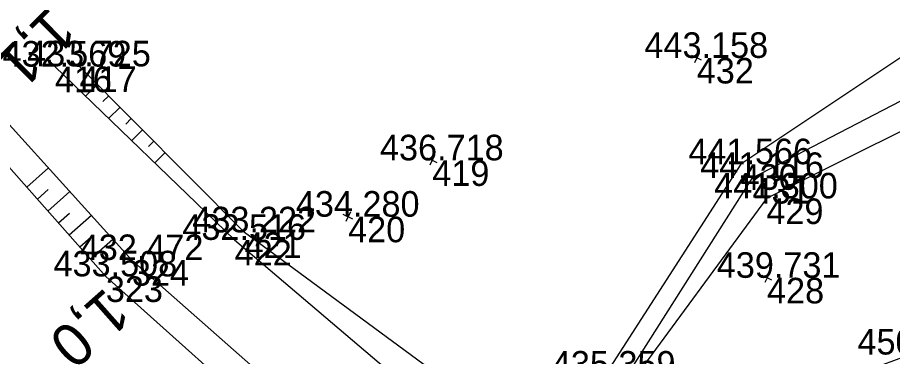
# Model space of a CAD drawing. Extents: x -751615 to -750797, y -1114905 to -1114561.
# Drawn here: x -751104.04 to -751063.01, y -1114657.37 to -1114641.47 of the extents above; entities that cross this region are included whole.
import ezdxf

# ---------------------------------------------------------------- set-up
doc = ezdxf.new("R2010")
doc.units = 0
for name, color, linetype in [('Vrstva 18', 7, 'Continuous'), ('Vrstva 48', 7, 'Continuous'), ('Vrstva 49', 7, 'Continuous'), ('Vrstva 50', 7, 'Continuous'), ('Vrstva 60', 7, 'Continuous'), ('Vrstva 61', 7, 'Continuous')]:
    doc.layers.add(name, color=color, linetype=linetype)

msp = doc.modelspace()

# ---------------------------------------------------------------- linework, layer by layer
at = {"layer": 'Vrstva 18'}
msp.add_ellipse((-751065.634, -1114658.626), major_axis=(5.471, 2.11), ratio=0.004805, start_param=0.014809, end_param=1.725149, dxfattribs=at)
at = {"layer": 'Vrstva 48'}
for p, q in [((-751100.291, -1114644.609), (-751100.846, -1114645.161)), ((-751099.762, -1114645.141), (-751100.034, -1114645.411)), ((-751099.234, -1114645.673), (-751099.766, -1114646.202)), ((-751098.705, -1114646.205), (-751098.966, -1114646.464)), ((-751098.176, -1114646.736), (-751098.686, -1114647.243)), ((-751097.647, -1114647.268), (-751097.897, -1114647.516)), ((-751097.119, -1114647.8), (-751097.606, -1114648.285)), ((-751103.607, -1114649.422), (-751102.589, -1114648.521)), ((-751103.11, -1114649.984), (-751102.598, -1114649.53)), ((-751102.613, -1114650.545), (-751101.582, -1114649.633)), ((-751102.115, -1114651.107), (-751101.597, -1114650.648)), ((-751101.618, -1114651.668), (-751100.576, -1114650.745)), ((-751101.121, -1114652.23), (-751100.597, -1114651.766)), ((-751100.624, -1114652.792), (-751099.569, -1114651.858))]:
    msp.add_line(p, q, dxfattribs=at)
at = {"layer": 'Vrstva 49'}
for p, q in [((-751071.962, -1114643.472), (-751072.412, -1114643.254)), ((-751072.078, -1114643.138), (-751072.296, -1114643.588)), ((-751084.363, -1114648.279), (-751084.813, -1114648.059)), ((-751084.478, -1114647.944), (-751084.698, -1114648.394)), ((-751088.311, -1114650.921), (-751088.761, -1114650.701)), ((-751088.426, -1114650.586), (-751088.646, -1114651.036)), ((-751068.666, -1114653.788), (-751069.116, -1114653.57)), ((-751068.782, -1114653.454), (-751069, -1114653.904))]:
    msp.add_line(p, q, dxfattribs=at)
for points in [[(-751116.675, -1114632.953), (-751098.674, -1114652.847), (-751090.21, -1114660.329), (-751083.98, -1114663.255), (-751079.08, -1114670.424), (-751065.412, -1114686.286)], [(-751117.644, -1114633.563), (-751099.898, -1114653.612), (-751091.377, -1114661.254), (-751084.998, -1114664.191), (-751079.852, -1114671.705), (-751066.794, -1114687.156)], [(-751020.117, -1114634.765), (-751060.04, -1114641.62), (-751070.127, -1114648.352), (-751076.528, -1114658.314), (-751078.11, -1114663.715)], [(-751019.246, -1114637.748), (-751058.49, -1114644.759), (-751068.921, -1114649.956), (-751075.459, -1114658.878), (-751078.11, -1114663.715)], [(-751102.288, -1114643.771), (-751093.857, -1114651.899), (-751082.797, -1114661.315), (-751076.158, -1114667.661), (-751071.168, -1114674.163), (-751065.653, -1114680.07)], [(-751078.11, -1114663.715), (-751081.827, -1114660.07), (-751093.394, -1114651.547), (-751101.134, -1114643.761)], [(-751078.11, -1114663.715), (-751075.662, -1114658.603), (-751069.572, -1114648.996), (-751058.95, -1114643.469)]]:
    msp.add_lwpolyline(points, dxfattribs=at)
at = {"layer": 'Vrstva 50'}
for points in [[(-751116.675, -1114632.953), (-751098.674, -1114652.847), (-751090.21, -1114660.329), (-751083.98, -1114663.255), (-751079.08, -1114670.424), (-751065.412, -1114686.286)], [(-751102.288, -1114643.771), (-751093.857, -1114651.899), (-751082.797, -1114661.315), (-751076.158, -1114667.661), (-751071.168, -1114674.163), (-751065.653, -1114680.07)]]:
    msp.add_lwpolyline(points, dxfattribs=at)
at = {"layer": 'Vrstva 60'}
for p, q in [((-751072.187, -1114643.363), (-751072.187, -1114643.363)), ((-751102.288, -1114643.771), (-751102.288, -1114643.771)), ((-751101.134, -1114643.761), (-751101.134, -1114643.761)), ((-751084.588, -1114648.169), (-751084.588, -1114648.169)), ((-751070.127, -1114648.352), (-751070.127, -1114648.352)), ((-751069.572, -1114648.996), (-751069.572, -1114648.996)), ((-751068.921, -1114649.956), (-751068.921, -1114649.956)), ((-751088.536, -1114650.811), (-751088.536, -1114650.811)), ((-751093.394, -1114651.547), (-751093.394, -1114651.547)), ((-751093.857, -1114651.899), (-751093.857, -1114651.899)), ((-751098.674, -1114652.847), (-751098.674, -1114652.847)), ((-751099.898, -1114653.612), (-751099.898, -1114653.612)), ((-751068.891, -1114653.679), (-751068.891, -1114653.679))]:
    msp.add_line(p, q, dxfattribs=at)

# ---------------------------------------------------------------- texts
at = {"layer": 'Vrstva 48'}
for s, rotation, p in [('1,1', 224.8302, (-751102.533, -1114640.88)), ('1,0', 221.5131, (-751099.911, -1114654.087))]:
    msp.add_text(s, height=2, rotation=rotation, dxfattribs=at).set_placement(p)
at = {"layer": 'Vrstva 60'}
for s, p in [('432', (-751072.187, -1114644.563)), ('416', (-751102.288, -1114644.971)), ('417', (-751101.134, -1114644.961)), ('419', (-751084.588, -1114649.369)), ('430', (-751070.127, -1114649.552)), ('431', (-751069.572, -1114650.196)), ('429', (-751068.921, -1114651.156)), ('420', (-751088.536, -1114652.011)), ('421', (-751093.394, -1114652.747)), ('422', (-751093.857, -1114653.099)), ('324', (-751098.674, -1114654.047)), ('323', (-751099.898, -1114654.812)), ('428', (-751068.891, -1114654.879))]:
    msp.add_text(s, height=1.2, dxfattribs=at).set_placement(p)
at = {"layer": 'Vrstva 61'}
for s, p in [('443.158', (-751074.641, -1114643.363)), ('432.569', (-751104.742, -1114643.771)), ('433.725', (-751103.59, -1114643.761)), ('436.718', (-751087.042, -1114648.169)), ('441.566', (-751072.579, -1114648.352)), ('441.116', (-751072.024, -1114648.996)), ('441.300', (-751071.372, -1114649.956)), ('434.280', (-751090.987, -1114650.811)), ('433.222', (-751095.842, -1114651.547)), ('432.516', (-751096.309, -1114651.899)), ('432.472', (-751101.122, -1114652.847)), ('433.508', (-751102.352, -1114653.612)), ('439.731', (-751071.248, -1114653.679)), ('450.834', (-751064.65, -1114657.277)), ('435.359', (-751078.982, -1114658.314))]:
    msp.add_text(s, height=1.2, dxfattribs=at).set_placement(p)

doc.saveas('drawing.dxf')
